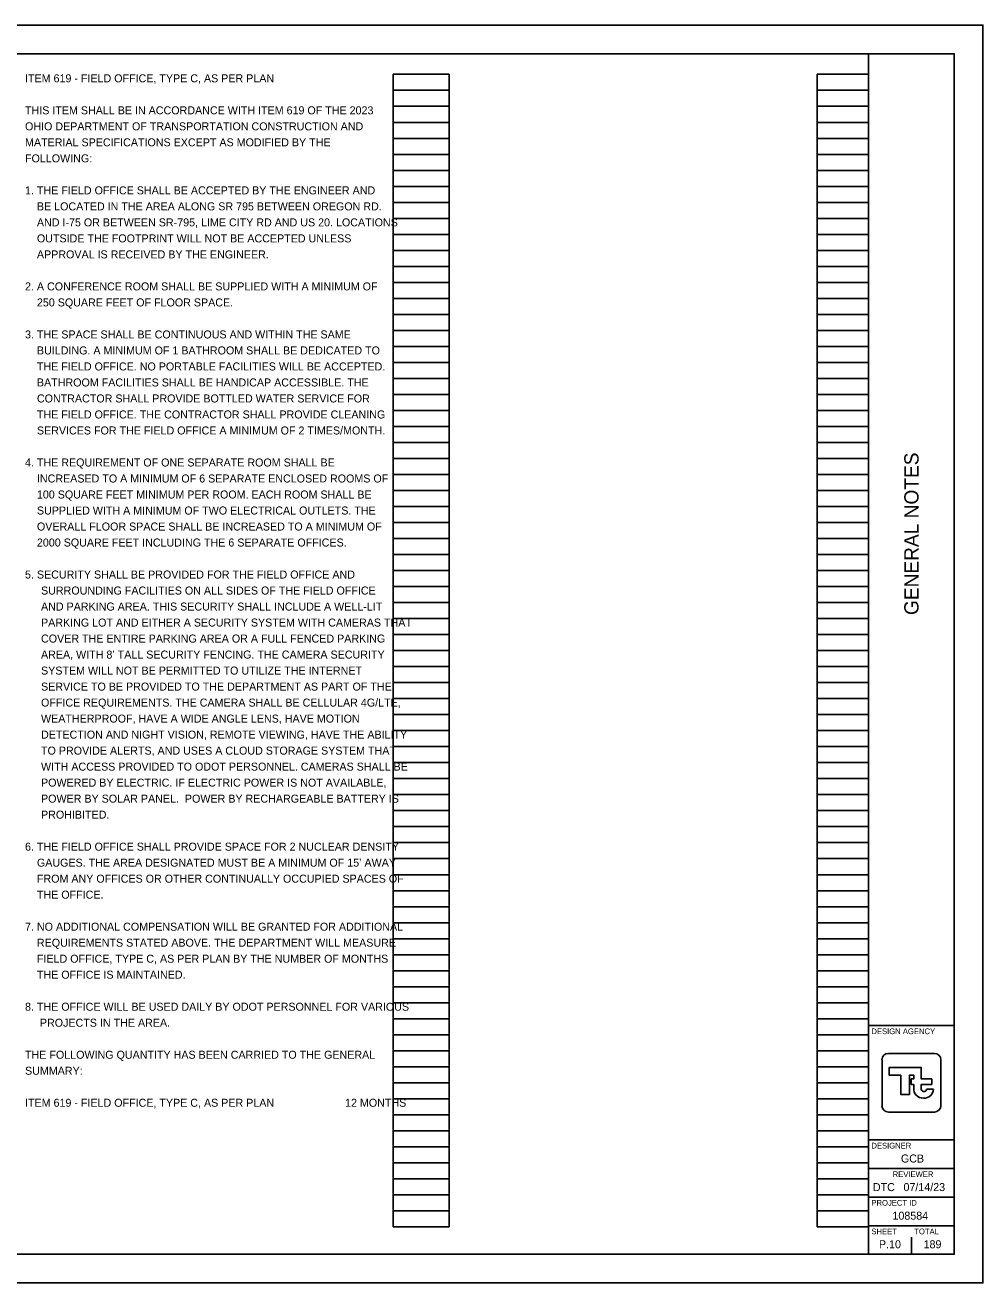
# Model space of a CAD drawing. Extents: x 0 to 34, y 0 to 22.
# Drawn here: x 17.24 to 34, y 0 to 22 of the extents above; entities that cross this region are included whole.
import ezdxf

# ---------------------------------------------------------------- set-up
doc = ezdxf.new("R2010")
doc.units = 0
for name, color, linetype in [('SH_Border', 7, 'Continuous'), ('SH_Cut_Line', 7, 'Continuous'), ('SH_Data', 7, 'Continuous'), ('SH_Text', 7, 'Continuous')]:
    doc.layers.add(name, color=color, linetype=linetype)

msp = doc.modelspace()

# ---------------------------------------------------------------- linework, layer by layer
at = {"layer": 'SH_Border'}
for p, q in [((32, 0.5), (32, 21.5)), ((32, 4.5), (33.5, 4.5)), ((32, 2.5), (33.5, 2.5)), ((32, 2), (33.5, 2)), ((32, 1.5), (33.5, 1.5)), ((32, 1), (33.5, 1))]:
    msp.add_line(p, q, dxfattribs=at)
msp.add_lwpolyline([(1.5, 21.5), (33.5, 21.5), (33.5, 0.5), (1.5, 0.5)], close=True, dxfattribs=at)
at = {"layer": 'SH_Cut_Line'}
msp.add_lwpolyline([(0, 0), (34, 0), (34, 22), (0, 22)], close=True, dxfattribs=at)
at = {"layer": 'SH_Data'}
for p, q in [((23.68, 0.98), (23.68, 21.14)), ((23.68, 21.14), (24.66, 21.14)), ((24.66, 0.98), (24.66, 21.14)), ((31.1, 0.98), (31.1, 21.14)), ((31.1, 21.14), (32, 21.14)), ((32, 0.98), (32, 21.14)), ((23.68, 20.86), (24.66, 20.86)), ((31.1, 20.86), (32, 20.86)), ((23.68, 20.58), (24.66, 20.58)), ((31.1, 20.58), (32, 20.58)), ((23.68, 20.3), (24.66, 20.3)), ((31.1, 20.3), (32, 20.3)), ((23.68, 20.02), (24.66, 20.02)), ((31.1, 20.02), (32, 20.02)), ((23.68, 19.74), (24.66, 19.74)), ((31.1, 19.74), (32, 19.74)), ((23.68, 19.46), (24.66, 19.46)), ((31.1, 19.46), (32, 19.46)), ((23.68, 19.18), (24.66, 19.18)), ((31.1, 19.18), (32, 19.18)), ((23.68, 18.9), (24.66, 18.9)), ((31.1, 18.9), (32, 18.9)), ((23.68, 18.62), (24.66, 18.62)), ((31.1, 18.62), (32, 18.62)), ((23.68, 18.34), (24.66, 18.34)), ((31.1, 18.34), (32, 18.34)), ((23.68, 18.06), (24.66, 18.06)), ((31.1, 18.06), (32, 18.06)), ((23.68, 17.78), (24.66, 17.78)), ((31.1, 17.78), (32, 17.78)), ((23.68, 17.5), (24.66, 17.5)), ((31.1, 17.5), (32, 17.5)), ((23.68, 17.22), (24.66, 17.22)), ((31.1, 17.22), (32, 17.22)), ((23.68, 16.94), (24.66, 16.94)), ((31.1, 16.94), (32, 16.94)), ((23.68, 16.66), (24.66, 16.66)), ((31.1, 16.66), (32, 16.66)), ((23.68, 16.38), (24.66, 16.38)), ((31.1, 16.38), (32, 16.38)), ((23.68, 16.1), (24.66, 16.1)), ((31.1, 16.1), (32, 16.1)), ((23.68, 15.82), (24.66, 15.82)), ((31.1, 15.82), (32, 15.82)), ((23.68, 15.54), (24.66, 15.54)), ((31.1, 15.54), (32, 15.54)), ((23.68, 15.26), (24.66, 15.26)), ((31.1, 15.26), (32, 15.26)), ((23.68, 14.98), (24.66, 14.98)), ((31.1, 14.98), (32, 14.98)), ((23.68, 14.7), (24.66, 14.7)), ((31.1, 14.7), (32, 14.7)), ((23.68, 14.42), (24.66, 14.42)), ((31.1, 14.42), (32, 14.42)), ((23.68, 14.14), (24.66, 14.14)), ((31.1, 14.14), (32, 14.14)), ((23.68, 13.86), (24.66, 13.86)), ((31.1, 13.86), (32, 13.86)), ((23.68, 13.58), (24.66, 13.58)), ((31.1, 13.58), (32, 13.58)), ((23.68, 13.3), (24.66, 13.3)), ((31.1, 13.3), (32, 13.3)), ((23.68, 13.02), (24.66, 13.02)), ((31.1, 13.02), (32, 13.02)), ((23.68, 12.74), (24.66, 12.74)), ((31.1, 12.74), (32, 12.74)), ((23.68, 12.46), (24.66, 12.46)), ((31.1, 12.46), (32, 12.46)), ((23.68, 12.18), (24.66, 12.18)), ((31.1, 12.18), (32, 12.18)), ((23.68, 11.9), (24.66, 11.9)), ((31.1, 11.9), (32, 11.9)), ((23.68, 11.62), (24.66, 11.62)), ((31.1, 11.62), (32, 11.62)), ((23.68, 11.34), (24.66, 11.34)), ((31.1, 11.34), (32, 11.34)), ((23.68, 11.06), (24.66, 11.06)), ((31.1, 11.06), (32, 11.06)), ((23.68, 10.78), (24.66, 10.78)), ((31.1, 10.78), (32, 10.78)), ((23.68, 10.5), (24.66, 10.5)), ((31.1, 10.5), (32, 10.5)), ((23.68, 10.22), (24.66, 10.22)), ((31.1, 10.22), (32, 10.22)), ((23.68, 9.94), (24.66, 9.94)), ((31.1, 9.94), (32, 9.94)), ((23.68, 9.66), (24.66, 9.66)), ((31.1, 9.66), (32, 9.66)), ((23.68, 9.38), (24.66, 9.38)), ((31.1, 9.38), (32, 9.38)), ((23.68, 9.1), (24.66, 9.1)), ((31.1, 9.1), (32, 9.1)), ((23.68, 8.82), (24.66, 8.82)), ((31.1, 8.82), (32, 8.82)), ((23.68, 8.54), (24.66, 8.54)), ((31.1, 8.54), (32, 8.54)), ((23.68, 8.26), (24.66, 8.26)), ((31.1, 8.26), (32, 8.26)), ((23.68, 7.98), (24.66, 7.98)), ((31.1, 7.98), (32, 7.98)), ((23.68, 7.7), (24.66, 7.7)), ((31.1, 7.7), (32, 7.7)), ((23.68, 7.42), (24.66, 7.42)), ((31.1, 7.42), (32, 7.42)), ((23.68, 7.14), (24.66, 7.14)), ((31.1, 7.14), (32, 7.14)), ((23.68, 6.86), (24.66, 6.86)), ((31.1, 6.86), (32, 6.86)), ((23.68, 6.58), (24.66, 6.58)), ((31.1, 6.58), (32, 6.58)), ((23.68, 6.3), (24.66, 6.3)), ((31.1, 6.3), (32, 6.3)), ((23.68, 6.02), (24.66, 6.02)), ((31.1, 6.02), (32, 6.02)), ((23.68, 5.74), (24.66, 5.74)), ((31.1, 5.74), (32, 5.74)), ((23.68, 5.46), (24.66, 5.46)), ((31.1, 5.46), (32, 5.46)), ((23.68, 5.18), (24.66, 5.18)), ((31.1, 5.18), (32, 5.18)), ((23.68, 4.9), (24.66, 4.9)), ((31.1, 4.9), (32, 4.9)), ((23.68, 4.62), (24.66, 4.62)), ((31.1, 4.62), (32, 4.62)), ((23.68, 4.34), (24.66, 4.34)), ((31.1, 4.34), (32, 4.34)), ((23.68, 4.06), (24.66, 4.06)), ((31.1, 4.06), (32, 4.06)), ((23.68, 3.78), (24.66, 3.78)), ((31.1, 3.78), (32, 3.78)), ((23.68, 3.5), (24.66, 3.5)), ((31.1, 3.5), (32, 3.5)), ((32.75, 3.5), (32.75, 3.5)), ((32.791, 3.415), (32.791, 3.415)), ((33.136, 3.385), (33.015, 3.385)), ((23.68, 3.22), (24.66, 3.22)), ((31.1, 3.22), (32, 3.22)), ((23.68, 2.94), (24.66, 2.94)), ((31.1, 2.94), (32, 2.94)), ((23.68, 2.66), (24.66, 2.66)), ((31.1, 2.66), (32, 2.66)), ((23.68, 2.38), (24.66, 2.38)), ((31.1, 2.38), (32, 2.38)), ((23.68, 2.1), (24.66, 2.1)), ((31.1, 2.1), (32, 2.1)), ((23.68, 1.82), (24.66, 1.82)), ((31.1, 1.82), (32, 1.82)), ((23.68, 1.54), (24.66, 1.54)), ((31.1, 1.54), (32, 1.54)), ((23.68, 1.26), (24.66, 1.26)), ((31.1, 1.26), (32, 1.26)), ((23.68, 0.98), (24.66, 0.98)), ((31.1, 0.98), (32, 0.98)), ((32.375, 0.675), (32.375, 0.675)), ((32.75, 0.5), (32.75, 0.8))]:
    msp.add_line(p, q, dxfattribs=at)
for points in [[(32.348, 4.014), (33.152, 4.014)], [(32.236, 3.099), (32.236, 3.901)], [(32.922, 3.399), (32.922, 3.47), (33.107, 3.47), (33.107, 3.568), (32.922, 3.568), (32.922, 3.768), (32.361, 3.768), (32.361, 3.632), (32.566, 3.632), (32.566, 3.294), (32.715, 3.294), (32.715, 3.63), (32.79, 3.63), (32.79, 3.568), (32.748, 3.568), (32.748, 3.47), (32.79, 3.47), (32.79, 3.415), (32.791, 3.415)], [(33.264, 3.901), (33.264, 3.099)], [(33.152, 2.986), (32.348, 2.986)]]:
    msp.add_lwpolyline(points, dxfattribs=at)
for centre, radius, start, end in [((32.348, 3.901), 0.113, 90, 180), ((33.152, 3.901), 0.113, 360, 90), ((32.949, 3.392), 0.16, 171.8856, 274.8323), ((32.968, 3.392), 0.0473, 171.8856, 350.9243), ((32.976, 3.392), 0.16, 265.1677, 357.3201), ((32.348, 3.099), 0.113, 180, 270), ((33.152, 3.099), 0.113, 270, 360)]:
    msp.add_arc(centre, radius, start, end, dxfattribs=at)

# ---------------------------------------------------------------- texts
msp.add_text('GENERAL NOTES', height=0.25, rotation=90, dxfattribs=at).set_placement((32.875, 11.682))
for s, height, p in [('DESIGN AGENCY', 0.1, (32.05, 4.35)), ('DESIGNER', 0.1, (32.05, 2.35)), ('GCB', 0.14, (32.566, 2.105)), ('REVIEWER', 0.1, (32.422, 1.85)), ('DTC', 0.14, (32.076, 1.605)), ('07/14/23', 0.14, (32.611, 1.605)), ('PROJECT ID', 0.1, (32.05, 1.35)), ('108584', 0.14, (32.418, 1.105)), ('SHEET', 0.1, (32.05, 0.85)), ('TOTAL', 0.1, (32.8, 0.85)), ('P.10', 0.14, (32.182, 0.605)), ('189', 0.14, (32.963, 0.605))]:
    msp.add_text(s, height=height, dxfattribs=at).set_placement(p)
at = {"layer": 'SH_Text'}
for s, p in [('ITEM 619 - FIELD OFFICE, TYPE C, AS PER PLAN', (17.24, 21)), ('THIS ITEM SHALL BE IN ACCORDANCE WITH ITEM 619 OF THE 2023', (17.24, 20.44)), ('OHIO DEPARTMENT OF TRANSPORTATION CONSTRUCTION AND', (17.24, 20.16)), ('MATERIAL SPECIFICATIONS EXCEPT AS MODIFIED BY THE', (17.24, 19.88)), ('FOLLOWING:', (17.24, 19.6)), ('1. THE FIELD OFFICE SHALL BE ACCEPTED BY THE ENGINEER AND', (17.24, 19.04)), ('    BE LOCATED IN THE AREA ALONG SR 795 BETWEEN OREGON RD.', (17.24, 18.76)), ('    AND I-75 OR BETWEEN SR-795,\xa0LIME CITY RD AND US 20. LOCATIONS', (17.24, 18.48)), ('    OUTSIDE THE FOOTPRINT WILL NOT BE ACCEPTED UNLESS', (17.24, 18.2)), ('    APPROVAL IS RECEIVED BY THE ENGINEER.', (17.24, 17.92)), ('2. A CONFERENCE ROOM SHALL BE SUPPLIED WITH A MINIMUM OF', (17.24, 17.36)), ('    250 SQUARE FEET OF FLOOR SPACE.', (17.24, 17.08)), ('3. THE SPACE SHALL BE CONTINUOUS AND WITHIN THE SAME', (17.24, 16.52)), ('    BUILDING. A MINIMUM OF 1 BATHROOM SHALL BE DEDICATED TO', (17.24, 16.24)), ('    THE FIELD OFFICE. NO PORTABLE FACILITIES WILL BE ACCEPTED.', (17.24, 15.96)), ('    BATHROOM FACILITIES SHALL BE HANDICAP ACCESSIBLE. THE', (17.24, 15.68)), ('    CONTRACTOR SHALL PROVIDE BOTTLED WATER SERVICE FOR', (17.24, 15.4)), ('    THE FIELD OFFICE. THE CONTRACTOR SHALL PROVIDE CLEANING', (17.24, 15.12)), ('    SERVICES FOR THE FIELD OFFICE A MINIMUM OF 2 TIMES/MONTH.', (17.24, 14.84)), ('4. THE REQUIREMENT OF ONE SEPARATE ROOM SHALL BE', (17.24, 14.28)), ('    INCREASED TO A MINIMUM OF 6 SEPARATE ENCLOSED ROOMS OF', (17.24, 14)), ('    100 SQUARE FEET MINIMUM PER ROOM. EACH ROOM SHALL BE', (17.24, 13.72)), ('    SUPPLIED WITH A MINIMUM OF TWO ELECTRICAL OUTLETS. THE', (17.24, 13.44)), ('    OVERALL FLOOR SPACE SHALL BE INCREASED TO A MINIMUM OF', (17.24, 13.16)), ('    2000 SQUARE FEET INCLUDING THE 6 SEPARATE OFFICES.', (17.24, 12.88)), ('5. SECURITY SHALL BE PROVIDED FOR THE FIELD OFFICE AND', (17.24, 12.32)), ('SURROUNDING FACILITIES ON ALL SIDES OF THE FIELD OFFICE', (17.52, 12.04)), ('AND PARKING AREA. THIS SECURITY SHALL INCLUDE A WELL-LIT ', (17.52, 11.76)), ('PARKING LOT AND EITHER A SECURITY SYSTEM WITH CAMERAS THAT ', (17.52, 11.48)), ('COVER THE ENTIRE PARKING AREA OR A FULL FENCED PARKING ', (17.52, 11.2)), ('AREA, WITH 8’ TALL SECURITY FENCING. THE CAMERA SECURITY ', (17.52, 10.92)), ('SYSTEM WILL NOT BE PERMITTED TO UTILIZE THE INTERNET ', (17.52, 10.64)), ('SERVICE TO BE PROVIDED TO THE DEPARTMENT AS PART OF THE ', (17.52, 10.36)), ('OFFICE REQUIREMENTS. THE CAMERA SHALL BE CELLULAR 4G/LTE, ', (17.52, 10.08)), ('WEATHERPROOF, HAVE A WIDE ANGLE LENS, HAVE MOTION ', (17.52, 9.8)), ('DETECTION AND NIGHT VISION, REMOTE VIEWING, HAVE THE ABILITY ', (17.52, 9.52)), ('TO PROVIDE ALERTS, AND USES A CLOUD STORAGE SYSTEM THAT ', (17.52, 9.24)), ('WITH ACCESS PROVIDED TO ODOT PERSONNEL. CAMERAS SHALL BE ', (17.52, 8.96)), ('POWERED BY ELECTRIC. IF ELECTRIC POWER IS NOT AVAILABLE, ', (17.52, 8.68)), ('POWER BY SOLAR PANEL.  POWER BY RECHARGEABLE BATTERY IS ', (17.52, 8.4)), ('PROHIBITED.', (17.52, 8.12)), ('6. THE FIELD OFFICE SHALL PROVIDE SPACE FOR 2 NUCLEAR DENSITY', (17.24, 7.56)), ('    GAUGES. THE AREA DESIGNATED MUST BE A MINIMUM OF 15’ AWAY', (17.24, 7.28)), ('    FROM ANY OFFICES OR OTHER CONTINUALLY OCCUPIED SPACES OF', (17.24, 7)), ('    THE OFFICE.', (17.24, 6.72)), ('7. NO ADDITIONAL COMPENSATION WILL BE GRANTED FOR ADDITIONAL', (17.24, 6.16)), ('    REQUIREMENTS STATED ABOVE. THE DEPARTMENT WILL MEASURE', (17.24, 5.88)), ('    FIELD OFFICE, TYPE C, AS PER PLAN BY THE NUMBER OF MONTHS', (17.24, 5.6)), ('    THE OFFICE IS MAINTAINED.', (17.24, 5.32)), ('8. THE OFFICE WILL BE USED DAILY BY ODOT PERSONNEL FOR VARIOUS', (17.24, 4.76)), ('     PROJECTS IN THE AREA.', (17.24, 4.48)), ('THE FOLLOWING QUANTITY HAS BEEN CARRIED TO THE GENERAL', (17.24, 3.92)), ('SUMMARY:', (17.24, 3.64)), ('ITEM 619 - FIELD OFFICE, TYPE C, AS PER PLAN ', (17.24, 3.08)), ('12 MONTHS', (22.84, 3.08))]:
    msp.add_text(s, height=0.14, dxfattribs=at).set_placement(p)

doc.saveas('drawing.dxf')
